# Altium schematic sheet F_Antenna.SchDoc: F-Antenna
size A4; Organization: Team- Ashwathama; Address1: Colroado Boulder; Address2: Author- Deepesh Sonigra; Address3: Self Checking Shopping Cart; DocumentNumber: 1; Revision: 1.0; SheetNumber: 6; SheetTotal: 7
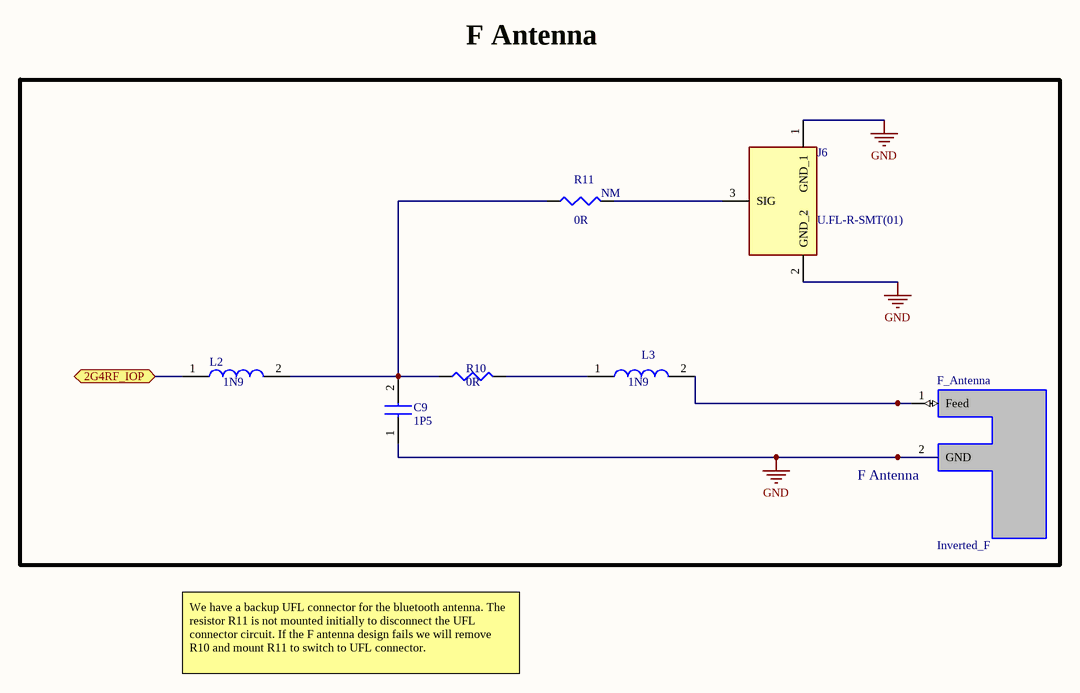
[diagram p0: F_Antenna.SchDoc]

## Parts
C9  value 1P5  [CAPC1005X55N]  (hidden comment: GRM1555C1H1R5WA01D)
F_Antenna  Inverted_F  [Inverted_F]
J6  U.FL-R-SMT(01)  [U.FL-R-SMT(01)]
L2  value 1N9  [INDC1005X45N]  (hidden comment: LQP15MN1N9W02D)
L3  value 1N9  [INDC1005X45N]  (hidden comment: LQP15MN1N9W02D)
R10  value 0R  [J1-0603]  (hidden comment: Res3)
R11  value 0R  Mounted: NM  [J1-0603]  (hidden comment: Res3)

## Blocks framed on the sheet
F Antenna: C9 F_Antenna J6 L2 L3 R10 R11

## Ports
2G4RF_IOP

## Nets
GND: C9.1 F_Antenna.2(GND) J6.1(GND_1) J6.2(GND_2)
2G4RF_IOP: L2.1 ; port 2G4RF_IOP
NetC9_2: C9.2 L2.2 R10.1 R11.1
NetF_Antenna_1: F_Antenna.1(Feed) L3.2
NetJ6_3: J6.3(SIG) R11.2
NetL3_1: L3.1 R10.2

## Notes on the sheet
- F Antenna
- We have a backup UFL connector for the bluetooth antenna. The resistor R11 is not mounted initially to disconnect the UFL connector circuit. If the F antenna design fails we will remove R10 and mount R11 to switch to UFL connector.

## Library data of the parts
C9 = GRM1555C1H1R5WA01D: Capacitor; Manufacturer_Name: Murata Electronics
J6 = U.FL-R-SMT(01): Connector; Manufacturer_Name: Hirose
L2 L3 = LQP15MN1N9W02D: Inductor; Manufacturer_Name: Murata Electronics
R10 R11 = Res3: Resistor; Manufacturer_Name: Vishay Dale; Manufacturer_Part_Number: CRCW06030000Z0EAHP; Detailed Description: 0 Ohms Jumper 0.25W, 1/4W Chip Resistor 0603 (1608 Metric) Automotive AEC-Q200, Pulse Withstanding Thick Film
